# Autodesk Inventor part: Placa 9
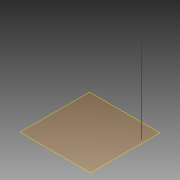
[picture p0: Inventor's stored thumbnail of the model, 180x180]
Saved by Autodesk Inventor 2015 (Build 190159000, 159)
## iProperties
Created: 2015-04
Part Number: Placa 9
Material: Generic
Document SubType Name: Modeling
Designer: suporte
Density: 1 g/cm^3
Appearance: Default
Author: suporte
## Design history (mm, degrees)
workplane "Work Plane1"
sketch "Sketch1"
  geometry: L1 (572.263, 887.5)-(572.263, 900) reference; L2 (572.263, 900)-(912.5, 560) reference; L3 (912.5, -900)-(912.5, 900) reference; L4 (572.263, 887.5)-(578.513, 893.754); L5 (572.263, 887.5)-(569.678, 884.912); L6 (569.678, 884.912)-(903.664, 551.158); L7 (912.5, 560)-(903.664, 551.158); 1 further point
  constraints: 8 end point, 3 perpendicular, 1 collinear, 1 point on line
  dimensions: "d0" = 12.5 distance from line of L2 L5.end
extrude "Extrusion1" new body sketch "Sketch1" distance "d1" = 2100; taper "d2" = 0 deg
body "Solid1"
node "Reference1"
node "Reference2"
node "Reference3"
